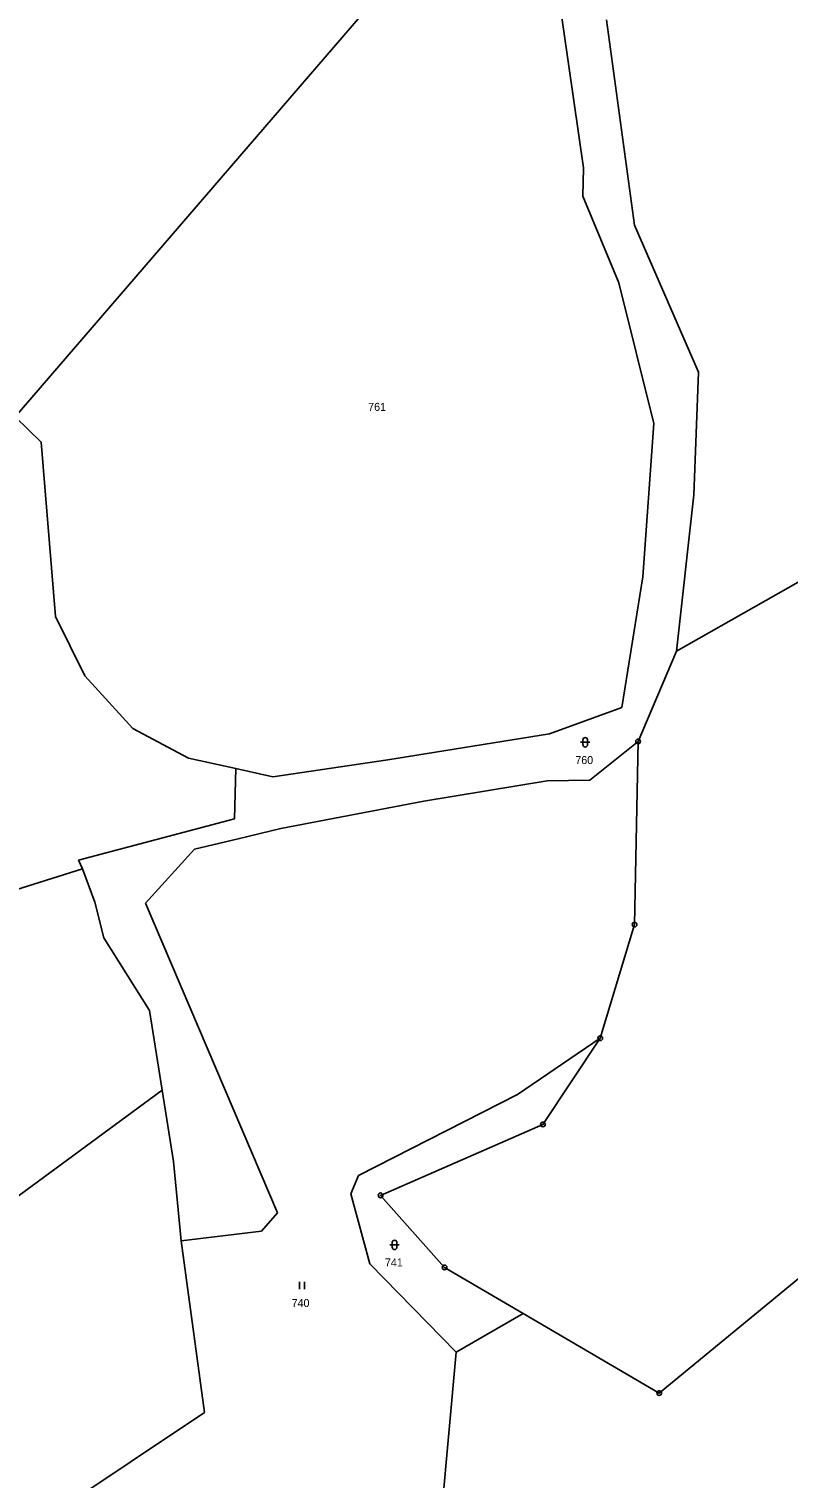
# Model space of a CAD drawing. Extents: x -719614 to -717765, y -1095834 to -1093862.
# Drawn here: x -718898.5 to -718737.1, y -1094490.2 to -1094182.4 of the extents above; entities that cross this region are included whole.
import ezdxf
from ezdxf.enums import TextEntityAlignment as Align

# ---------------------------------------------------------------- set-up
doc = ezdxf.new("R2010")
doc.units = 0
doc.header["$LTSCALE"] = 0.68
for name, color, linetype, lineweight in [('1', 7, 'Continuous', 25), ('3', 7, 'Continuous', 25), ('8', 7, 'Continuous', 25)]:
    doc.layers.add(name, color=color, linetype=linetype, lineweight=lineweight)
doc.layers.add('2', color=7, linetype='Continuous')

msp = doc.modelspace()

# ---------------------------------------------------------------- linework, layer by layer
at = {"layer": '1'}
for p, q in [((-718901.4, -1094264.73), (-718792.98, -1094138.94)), ((-718780.62, -1094211.83), (-718785.85, -1094175.19)), ((-718769.79, -1094224), (-718775.69, -1094180.41)), ((-718780.73, -1094217.84), (-718780.62, -1094211.83)), ((-718773.1, -1094236.31), (-718780.73, -1094217.84)), ((-718756.12, -1094255.25), (-718769.79, -1094224)), ((-718765.68, -1094266.19), (-718773.1, -1094236.31)), ((-718757.11, -1094281.36), (-718756.12, -1094255.25)), ((-718895.91, -1094270.11), (-718901.4, -1094264.73)), ((-718768.01, -1094298.78), (-718765.68, -1094266.19)), ((-718892.82, -1094307.16), (-718895.91, -1094270.11)), ((-718760.81, -1094314.57), (-718757.11, -1094281.36)), ((-718725.22, -1094294.33), (-718760.81, -1094314.57)), ((-718772.48, -1094326.53), (-718768.01, -1094298.78)), ((-718886.58, -1094319.79), (-718892.82, -1094307.16)), ((-718768.98, -1094333.7), (-718760.81, -1094314.57)), ((-718876.39, -1094330.98), (-718886.58, -1094319.79)), ((-718787.85, -1094332.11), (-718772.48, -1094326.53)), ((-718864.56, -1094337.27), (-718876.39, -1094330.98)), ((-718822.21, -1094337.61), (-718787.85, -1094332.11)), ((-718779.24, -1094341.97), (-718768.98, -1094333.7)), ((-718768.98, -1094333.7), (-718769.73, -1094372.61)), ((-718854.51, -1094339.5), (-718864.56, -1094337.27)), ((-718846.64, -1094341.25), (-718822.21, -1094337.61)), ((-718854.77, -1094350.16), (-718854.51, -1094339.5)), ((-718854.51, -1094339.5), (-718846.64, -1094341.25)), ((-718814.54, -1094346.41), (-718788.32, -1094342.1)), ((-718788.32, -1094342.1), (-718779.24, -1094341.97)), ((-718844.96, -1094352.19), (-718814.54, -1094346.41)), ((-718887.92, -1094358.93), (-718854.77, -1094350.16)), ((-718863.28, -1094356.62), (-718854.02, -1094354.38)), ((-718854.02, -1094354.38), (-718844.96, -1094352.19)), ((-718873.67, -1094368.07), (-718863.28, -1094356.62)), ((-718887.07, -1094360.81), (-718887.92, -1094358.93)), ((-718905.73, -1094366.61), (-718887.07, -1094360.81)), ((-718884.44, -1094367.86), (-718887.07, -1094360.81)), ((-718882.53, -1094375.46), (-718884.44, -1094367.86)), ((-718845.65, -1094433.88), (-718873.67, -1094368.07)), ((-718769.73, -1094372.61), (-718777.03, -1094396.77)), ((-718872.87, -1094390.86), (-718882.53, -1094375.46)), ((-718870.17, -1094407.82), (-718872.87, -1094390.86)), ((-718777.03, -1094396.77), (-718794.63, -1094408.73)), ((-718789.24, -1094415.08), (-718777.03, -1094396.77)), ((-718962.29, -1094475.45), (-718870.17, -1094407.82)), ((-718870.17, -1094407.82), (-718867.76, -1094422.93)), ((-718794.63, -1094408.73), (-718828.41, -1094425.93)), ((-718823.73, -1094430.15), (-718789.24, -1094415.08)), ((-718867.76, -1094422.93), (-718866.11, -1094439.84)), ((-718828.41, -1094425.93), (-718830.02, -1094429.8)), ((-718830.02, -1094429.8), (-718826.04, -1094444.69)), ((-718810.13, -1094445.45), (-718823.73, -1094430.15)), ((-718764.5, -1094472.16), (-718713.88, -1094430.51)), ((-718849.01, -1094437.77), (-718845.65, -1094433.88)), ((-718866.11, -1094439.84), (-718849.01, -1094437.77)), ((-718866.11, -1094439.84), (-718861.16, -1094476.31)), ((-718826.04, -1094444.69), (-718807.67, -1094463.47)), ((-718793.42, -1094455.23), (-718810.13, -1094445.45)), ((-718807.67, -1094463.47), (-718793.42, -1094455.23)), ((-718793.42, -1094455.23), (-718764.5, -1094472.16)), ((-718811.08, -1094501.08), (-718807.67, -1094463.47)), ((-718861.16, -1094476.31), (-718937.45, -1094527.15))]:
    msp.add_line(p, q, dxfattribs=at)
at = {"layer": '3'}
for p, q in [((-718781.241, -1094333.901), (-718779.239, -1094333.901)), ((-718780.741, -1094333.401), (-718780.741, -1094334.402)), ((-718779.739, -1094334.402), (-718779.739, -1094333.401)), ((-718821.251, -1094440.181), (-718821.251, -1094441.182)), ((-718820.249, -1094441.182), (-718820.249, -1094440.181)), ((-718821.751, -1094440.681), (-718819.749, -1094440.681)), ((-718840.931, -1094450.05), (-718840.931, -1094448.55)), ((-718839.93, -1094450.05), (-718839.93, -1094448.55))]:
    msp.add_line(p, q, dxfattribs=at)
for centre, start, end in [((-718780.24, -1094333.4009), 0, 180), ((-718780.24, -1094334.4009), 180, 359.98789), ((-718820.75, -1094440.1809), 0, 180), ((-718820.75, -1094441.1809), 180, 359.98789)]:
    msp.add_arc(centre, 0.5, start, end, dxfattribs=at)
at = {"layer": '8'}
for centre, radius in [((-718768.98, -1094333.6999), 0.5), ((-718768.98, -1094333.6999), 0.0303), ((-718769.73, -1094372.6099), 0.5), ((-718769.73, -1094372.6099), 0.0303), ((-718777.03, -1094396.7699), 0.5), ((-718777.03, -1094396.7699), 0.0303), ((-718789.24, -1094415.0799), 0.5), ((-718789.24, -1094415.0799), 0.0303), ((-718823.73, -1094430.1499), 0.5), ((-718823.73, -1094430.1499), 0.0303), ((-718810.13, -1094445.4499), 0.5), ((-718810.13, -1094445.4499), 0.0303), ((-718764.5, -1094472.1599), 0.5), ((-718764.5, -1094472.1599), 0.0303)]:
    msp.add_circle(centre, radius, dxfattribs=at)

# ---------------------------------------------------------------- texts
at = {"layer": '2'}
for s, p in [('761', (-718824.469, -1094263.482)), ('760', (-718780.439, -1094338.522)), ('741', (-718820.909, -1094445.262)), ('740', (-718840.739, -1094453.872))]:
    msp.add_text(s, height=1.7, dxfattribs=at).set_placement(p, align=Align.CENTER)

doc.saveas('drawing.dxf')
